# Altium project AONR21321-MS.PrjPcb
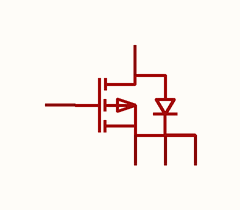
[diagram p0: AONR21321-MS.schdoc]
1 sheet, 1 parts. Net scope: global (net labels, ports and power ports of the same name join across sheets).

## Sheet AONR21321-MS.schdoc
size 127 x 101 mm

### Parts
Q?  aonr21321-ms  [TDSON-8_L5.9-W5.2-P1.27-BL]  (value not drawn)

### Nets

Not connected (* = marked no-connect by the designer): Q? 1(S) 2(S) 3(S) 4(G) 5(D)

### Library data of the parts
Q? = aonr21321-ms: 数量:1个P沟道;漏源电压(Vdss):30V;连续漏极电流(Id):50A;导通电阻(RDS(on)):25mΩ@4.5V;耗散功率(Pd):3W;阈值电压(Vgs(th)):3V;; Manufacturer: MSKSEMI(美森科); AddInBom: yes; ModelId: ff3d8edf19694f3eb1c5df98919f3bc8; ModelTransform: 216.9287,242.5192,0,0,0,0,0,43.307,0; Number: 1个P沟道; Drain to Source Voltage: 30V; Current - Continuous Drain(Id): 50A; Pd - Power Dissipation: 3W; Gate Threshold Voltage (Vgs(th)): 3V; Gate Charge(Qg): 24nC@10V; Input Capacitance(Ciss): 1.75nF; Reverse Transfer Capacitance (Crss@Vds): 180pF; Type: P沟道; Output Capacitance(Coss): 215pF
